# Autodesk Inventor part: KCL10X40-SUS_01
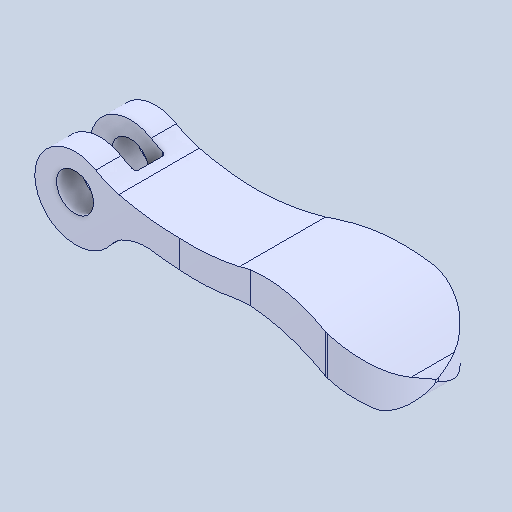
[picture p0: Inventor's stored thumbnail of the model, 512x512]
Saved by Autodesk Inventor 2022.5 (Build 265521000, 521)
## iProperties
Created: 2024-08
Part Number: KCL10X40-SUS_01
Material: 一般
Document SubType Name: Modeling
Designer: ImaoCorp
Density: 1 g/cm^3
Appearance: 既定
Author: ImaoCorp
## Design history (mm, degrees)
feature "KCL10X40-SUS_01"
node "ソリッド1"
